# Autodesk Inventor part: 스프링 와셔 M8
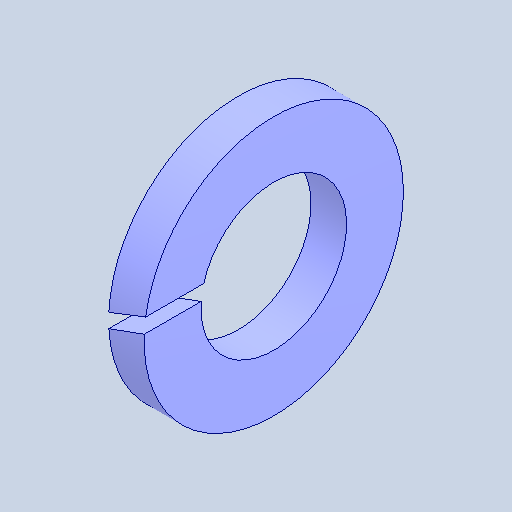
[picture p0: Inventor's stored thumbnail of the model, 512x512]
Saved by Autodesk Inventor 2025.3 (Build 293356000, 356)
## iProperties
Created: 2025-10
Part Number: 스프링 와셔 M8
Material: 강철, 연강
Description: 스프링 잠금 와셔
Document SubType Name: Modeling
Designer: USER
Density: 7.85 g/cm^3
Appearance: 기본값
Author: jhkim
Sending System: Autodesk Inventor 2026
Preprocessor: ST-DEVELOPER v20.1
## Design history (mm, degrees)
feature "Solid1"
node "솔리드1"
